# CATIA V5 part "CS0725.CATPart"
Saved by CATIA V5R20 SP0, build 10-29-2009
Part number: CS0725
Revision: 6
Definition: design
Nomenclature: CS0725
Source: made
Description: NOT SPECIFIED
Bounding box of the stored display mesh (mm): x -23.825 to 24, y -24 to 24, z -45 to 12
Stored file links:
  C:\Users\Raffaele\Desktop\3D X SITO CF\BOLEX\20-TILTED COLUMN SUPPORT\CS0725.CATPart
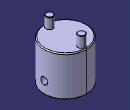
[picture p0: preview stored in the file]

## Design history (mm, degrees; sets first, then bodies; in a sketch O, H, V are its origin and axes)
Body1 "MANIFOLD_SOLID_BREP #711" (main body)
  Solid1: solid without history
